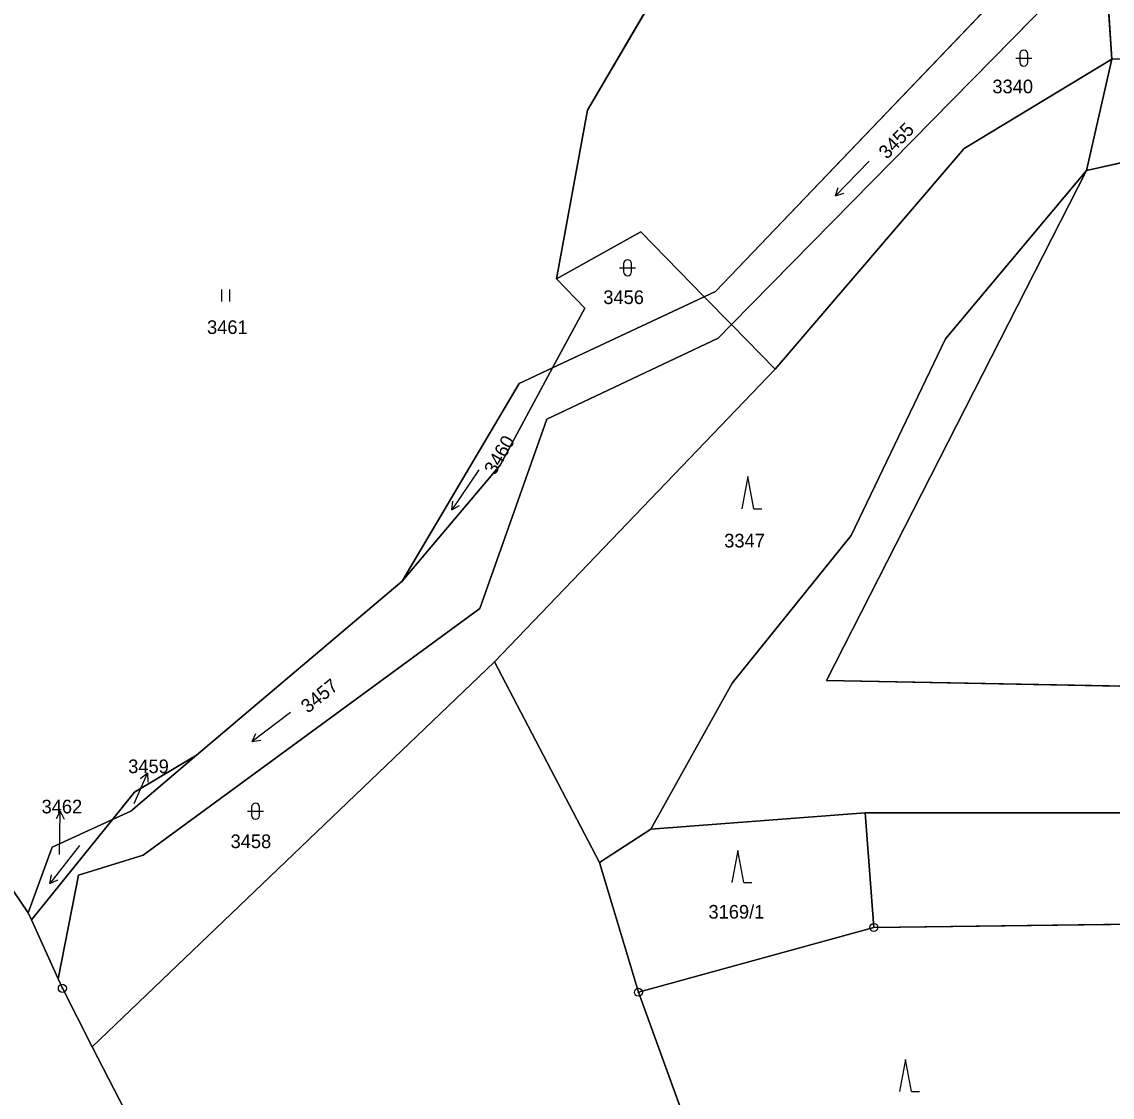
# Model space of a CAD drawing. Extents: x -689422 to -685210, y -987725 to -982160.
# Drawn here: x -688480.4 to -688344.6, y -984667.7 to -984533.7 of the extents above; entities that cross this region are included whole.
import ezdxf

# ---------------------------------------------------------------- set-up
doc = ezdxf.new("R2010")
doc.units = 0
for name, color, linetype in [('KN_Hranice obce', 7, 'Continuous'), ('KN_Hranice_katastrální území', 7, 'Continuous'), ('KN_Hranice_parcel', 7, 'Continuous'), ('KN_Parcelni cisla', 7, 'Continuous'), ('KN_Parcelni cisla_sipky', 7, 'Continuous'), ('KN_Polygon parcely', 7, 'Continuous'), ('KN_POZEMKY_LESNI POZEMEK', 7, 'Continuous'), ('KN_POZEMKY_OSTATNI PLOCHA', 7, 'Continuous'), ('KN_POZEMKY_TTP', 7, 'Continuous'), ('KN_POZEMKY_VODNI_PLOCHA', 7, 'Continuous'), ('KN_VYUZITI_07_vodni plocha_tok prirozeny', 7, 'Continuous'), ('KN_VYUZITI_27_ostatni plocha_neplodna puda', 7, 'Continuous'), ('KN_Značky bodu BP', 7, 'Continuous'), ('KN_Značky kultur', 7, 'Continuous')]:
    doc.layers.add(name, color=color, linetype=linetype)

msp = doc.modelspace()

# ---------------------------------------------------------------- linework, layer by layer
at = {"layer": 'KN_Hranice obce'}
msp.add_lwpolyline([(-688502.72, -984532.63), (-688500.95, -984546), (-688500.08, -984552.55), (-688496.2, -984562.92), (-688492.04, -984574.01), (-688494.32, -984588.16), (-688498.88, -984616.48), (-688486.18, -984635.03), (-688479.56, -984644.71), (-688479.18, -984645.55), (-688475.85, -984652.92), (-688475.32, -984654.1), (-688471.59, -984661.37), (-688463.53, -984677.08), (-688459.34, -984687.45), (-688479.39, -984708.23), (-688494.26, -984728.04)], dxfattribs=at)
at = {"layer": 'KN_Hranice_katastrální území'}
msp.add_lwpolyline([(-688502.72, -984532.63), (-688500.95, -984546), (-688500.08, -984552.55), (-688496.2, -984562.92), (-688492.04, -984574.01), (-688494.32, -984588.16), (-688498.88, -984616.48), (-688486.18, -984635.03), (-688479.56, -984644.71), (-688479.18, -984645.55), (-688475.85, -984652.92), (-688475.32, -984654.1), (-688471.59, -984661.37), (-688463.53, -984677.08), (-688459.34, -984687.45), (-688479.39, -984708.23), (-688494.26, -984728.04)], dxfattribs=at)
at = {"layer": 'KN_Hranice_parcel'}
for p, q in [((-688393.96, -984567.31), (-688351.07, -984522.41)), ((-688344.6, -984538.37), (-688345.32, -984527.81)), ((-688264.04, -984536.89), (-688344.6, -984538.37)), ((-688344.6, -984538.37), (-688347.76, -984552.23)), ((-688347.76, -984552.23), (-688325.28, -984547.24)), ((-688395.37, -984567.97), (-688393.96, -984567.31)), ((-688414.26, -984576.82), (-688395.37, -984567.97)), ((-688395.37, -984567.97), (-688391.99, -984571.43)), ((-688393.64, -984573.11), (-688391.99, -984571.43)), ((-688391.99, -984571.43), (-688386.56, -984576.97)), ((-688386.56, -984576.97), (-688421.5, -984613.44)), ((-688414.26, -984576.82), (-688418.41, -984578.76)), ((-688418.41, -984578.76), (-688433.02, -984603.38)), ((-688433.02, -984603.38), (-688458.61, -984625.07)), ((-688421.5, -984613.44), (-688471.59, -984661.37)), ((-688408.44, -984638.43), (-688421.5, -984613.44)), ((-688402.01, -984634.28), (-688375.35, -984632.24)), ((-688375.35, -984632.24), (-688374.25, -984646.51)), ((-688283.04, -984632.26), (-688375.35, -984632.24)), ((-688469.06, -984633.06), (-688479.18, -984645.55)), ((-688476.58, -984636.51), (-688469.06, -984633.06)), ((-688408.44, -984638.43), (-688402.01, -984634.28)), ((-688486.18, -984635.03), (-688479.56, -984644.71)), ((-688479.56, -984644.71), (-688476.58, -984636.51)), ((-688403.58, -984654.59), (-688408.44, -984638.43)), ((-688479.56, -984644.71), (-688479.18, -984645.55)), ((-688479.18, -984645.55), (-688475.85, -984652.92)), ((-688403.58, -984654.59), (-688374.25, -984646.51)), ((-688475.85, -984652.92), (-688475.32, -984654.1)), ((-688475.32, -984654.1), (-688471.59, -984661.37)), ((-688386.37, -984701.91), (-688403.58, -984654.59)), ((-688471.59, -984661.37), (-688463.53, -984677.08))]:
    msp.add_line(p, q, dxfattribs=at)
for points in [[(-688389.76, -984517.46), (-688397.31, -984523.2), (-688409.93, -984544.71), (-688413.76, -984565.73)], [(-688345.32, -984527.81), (-688349.54, -984528.23), (-688391.99, -984571.43)], [(-688386.56, -984576.97), (-688363, -984549.48), (-688344.6, -984538.37)], [(-688325.28, -984547.24), (-688269.48, -984546.51), (-688283.23, -984617.59), (-688380.15, -984615.76), (-688347.76, -984552.23)], [(-688347.76, -984552.23), (-688365.33, -984573.19), (-688377.06, -984597.71), (-688391.91, -984616.11), (-688402.01, -984634.28)], [(-688413.76, -984565.73), (-688403.27, -984559.89), (-688395.37, -984567.97)], [(-688413.76, -984565.73), (-688410.25, -984569.39), (-688414.26, -984576.82)], [(-688475.85, -984652.92), (-688473.33, -984640), (-688465.25, -984637.52), (-688423.32, -984606.79), (-688414.98, -984583.19), (-688393.64, -984573.11)], [(-688414.26, -984576.82), (-688420.8, -984588.94), (-688433.02, -984603.38)], [(-688458.61, -984625.07), (-688466.81, -984632.02), (-688469.06, -984633.06)], [(-688458.61, -984625.07), (-688466.33, -984629.68), (-688469.06, -984633.06)], [(-688374.25, -984646.51), (-688339.25, -984646.06), (-688339.83, -984661.97)]]:
    msp.add_lwpolyline(points, dxfattribs=at)
at = {"layer": 'KN_Parcelni cisla_sipky'}
for p, q in [((-688465.93, -984630.03), (-688464.71, -984627.29)), ((-688464.71, -984627.29), (-688465.57, -984628)), ((-688464.71, -984627.29), (-688464.66, -984628.41)), ((-688466.39, -984631.07), (-688465.93, -984630.03)), ((-688475.58, -984632.02), (-688476.1, -984633.01)), ((-688475.63, -984635.02), (-688475.58, -984632.02)), ((-688475.58, -984632.02), (-688475.09, -984633.03)), ((-688475.68, -984637.43), (-688475.63, -984635.02))]:
    msp.add_line(p, q, dxfattribs=at)
at = {"layer": 'KN_Polygon parcely'}
for points in [[(-688391.99, -984571.43), (-688349.54, -984528.23), (-688345.32, -984527.81), (-688345.35, -984525.63), (-688339.26, -984521.78), (-688328.95, -984520.44), (-688351.07, -984522.41), (-688393.96, -984567.31), (-688395.37, -984567.97)], [(-688282.78, -984521.59), (-688286.16, -984521.96), (-688345.32, -984527.81), (-688344.6, -984538.37), (-688264.04, -984536.89), (-688262.67, -984524.58)], [(-688386.56, -984576.97), (-688363, -984549.48), (-688344.6, -984538.37), (-688345.32, -984527.81), (-688349.54, -984528.23), (-688391.99, -984571.43)], [(-688344.6, -984538.37), (-688347.76, -984552.23), (-688325.28, -984547.24), (-688310.8, -984539.52), (-688264.46, -984540.61), (-688264.04, -984536.89)], [(-688402.01, -984634.28), (-688391.91, -984616.11), (-688377.06, -984597.71), (-688365.33, -984573.19), (-688347.76, -984552.23), (-688344.6, -984538.37), (-688363, -984549.48), (-688386.56, -984576.97), (-688421.5, -984613.44), (-688408.44, -984638.43)], [(-688264.46, -984540.61), (-688310.8, -984539.52), (-688325.28, -984547.24), (-688269.48, -984546.51), (-688283.23, -984617.59), (-688380.15, -984615.76), (-688347.76, -984552.23), (-688365.33, -984573.19), (-688377.06, -984597.71), (-688391.91, -984616.11), (-688402.01, -984634.28), (-688375.35, -984632.24), (-688283.04, -984632.26)], [(-688347.76, -984552.23), (-688380.15, -984615.76), (-688283.23, -984617.59), (-688269.48, -984546.51), (-688325.28, -984547.24)], [(-688414.26, -984576.82), (-688395.37, -984567.97), (-688403.27, -984559.89), (-688413.76, -984565.73), (-688410.25, -984569.39)], [(-688420.8, -984588.94), (-688433.02, -984603.38), (-688458.61, -984625.07), (-688466.81, -984632.02), (-688469.06, -984633.06), (-688479.18, -984645.55), (-688475.85, -984652.92), (-688473.33, -984640), (-688465.25, -984637.52), (-688423.32, -984606.79), (-688414.98, -984583.19), (-688393.64, -984573.11), (-688391.99, -984571.43), (-688395.37, -984567.97), (-688414.26, -984576.82)], [(-688471.59, -984661.37), (-688421.5, -984613.44), (-688386.56, -984576.97), (-688391.99, -984571.43), (-688393.64, -984573.11), (-688414.98, -984583.19), (-688423.32, -984606.79), (-688465.25, -984637.52), (-688473.33, -984640), (-688475.85, -984652.92), (-688475.32, -984654.1)], [(-688433.02, -984603.38), (-688420.8, -984588.94), (-688414.26, -984576.82), (-688418.41, -984578.76)], [(-688386.37, -984701.91), (-688403.58, -984654.59), (-688408.44, -984638.43), (-688421.5, -984613.44), (-688471.59, -984661.37), (-688463.53, -984677.08), (-688459.34, -984687.45), (-688430.5, -984736.06), (-688410.52, -984717.05), (-688390.36, -984704.33)], [(-688469.06, -984633.06), (-688466.81, -984632.02), (-688458.61, -984625.07), (-688466.33, -984629.68)], [(-688374.25, -984646.51), (-688375.35, -984632.24), (-688402.01, -984634.28), (-688408.44, -984638.43), (-688403.58, -984654.59)], [(-688283.04, -984632.26), (-688375.35, -984632.24), (-688374.25, -984646.51), (-688339.25, -984646.06), (-688339.83, -984661.97), (-688289.9, -984666.83)], [(-688479.18, -984645.55), (-688469.06, -984633.06), (-688476.58, -984636.51), (-688479.56, -984644.71)], [(-688373.26, -984693.97), (-688358.53, -984688.95), (-688347.01, -984687.83), (-688343.07, -984688.32), (-688339.83, -984661.97), (-688339.25, -984646.06), (-688374.25, -984646.51), (-688403.58, -984654.59), (-688386.37, -984701.91)]]:
    msp.add_lwpolyline(points, close=True, dxfattribs=at)
for points in [[(-688397.31, -984523.2), (-688409.93, -984544.71), (-688413.76, -984565.73), (-688403.27, -984559.89), (-688395.37, -984567.97), (-688393.96, -984567.31), (-688351.07, -984522.41)], [(-688502.72, -984532.63), (-688500.95, -984546), (-688500.08, -984552.55), (-688496.2, -984562.92), (-688492.04, -984574.01), (-688494.32, -984588.16), (-688498.88, -984616.48), (-688486.18, -984635.03), (-688479.56, -984644.71), (-688476.58, -984636.51), (-688469.06, -984633.06), (-688466.33, -984629.68), (-688458.61, -984625.07), (-688433.02, -984603.38), (-688418.41, -984578.76), (-688414.26, -984576.82), (-688410.25, -984569.39), (-688413.76, -984565.73), (-688409.93, -984544.71), (-688397.31, -984523.2)]]:
    msp.add_lwpolyline(points, dxfattribs=at)
at = {"layer": 'KN_POZEMKY_LESNI POZEMEK'}
for p, q in [((-688363, -984549.48), (-688344.6, -984538.37)), ((-688344.6, -984538.37), (-688347.76, -984552.23)), ((-688386.56, -984576.97), (-688363, -984549.48)), ((-688347.76, -984552.23), (-688380.15, -984615.76)), ((-688365.33, -984573.19), (-688347.76, -984552.23)), ((-688347.76, -984552.23), (-688365.33, -984573.19)), ((-688377.06, -984597.71), (-688365.33, -984573.19)), ((-688365.33, -984573.19), (-688377.06, -984597.71)), ((-688421.5, -984613.44), (-688386.56, -984576.97)), ((-688391.91, -984616.11), (-688377.06, -984597.71)), ((-688377.06, -984597.71), (-688391.91, -984616.11)), ((-688471.59, -984661.37), (-688421.5, -984613.44)), ((-688421.5, -984613.44), (-688408.44, -984638.43)), ((-688408.44, -984638.43), (-688421.5, -984613.44)), ((-688402.01, -984634.28), (-688391.91, -984616.11)), ((-688391.91, -984616.11), (-688402.01, -984634.28)), ((-688380.15, -984615.76), (-688283.23, -984617.59)), ((-688402.01, -984634.28), (-688375.35, -984632.24)), ((-688375.35, -984632.24), (-688402.01, -984634.28)), ((-688375.35, -984632.24), (-688374.25, -984646.51)), ((-688374.25, -984646.51), (-688375.35, -984632.24)), ((-688375.35, -984632.24), (-688283.04, -984632.26)), ((-688283.04, -984632.26), (-688375.35, -984632.24)), ((-688408.44, -984638.43), (-688402.01, -984634.28)), ((-688402.01, -984634.28), (-688408.44, -984638.43)), ((-688403.58, -984654.59), (-688408.44, -984638.43)), ((-688408.44, -984638.43), (-688403.58, -984654.59)), ((-688374.25, -984646.51), (-688403.58, -984654.59)), ((-688403.58, -984654.59), (-688374.25, -984646.51)), ((-688374.25, -984646.51), (-688339.25, -984646.06)), ((-688339.25, -984646.06), (-688374.25, -984646.51)), ((-688386.37, -984701.91), (-688403.58, -984654.59)), ((-688403.58, -984654.59), (-688386.37, -984701.91)), ((-688463.53, -984677.08), (-688471.59, -984661.37))]:
    msp.add_line(p, q, dxfattribs=at)
at = {"layer": 'KN_POZEMKY_OSTATNI PLOCHA'}
for p, q in [((-688351.07, -984522.41), (-688393.96, -984567.31)), ((-688409.93, -984544.71), (-688397.31, -984523.2)), ((-688391.99, -984571.43), (-688349.54, -984528.23)), ((-688345.32, -984527.81), (-688344.6, -984538.37)), ((-688344.6, -984538.37), (-688345.32, -984527.81)), ((-688264.04, -984536.89), (-688344.6, -984538.37)), ((-688344.6, -984538.37), (-688264.04, -984536.89)), ((-688344.6, -984538.37), (-688363, -984549.48)), ((-688347.76, -984552.23), (-688344.6, -984538.37)), ((-688413.76, -984565.73), (-688409.93, -984544.71)), ((-688325.28, -984547.24), (-688347.76, -984552.23)), ((-688363, -984549.48), (-688386.56, -984576.97)), ((-688413.76, -984565.73), (-688403.27, -984559.89)), ((-688403.27, -984559.89), (-688413.76, -984565.73)), ((-688403.27, -984559.89), (-688395.37, -984567.97)), ((-688395.37, -984567.97), (-688403.27, -984559.89)), ((-688410.25, -984569.39), (-688413.76, -984565.73)), ((-688393.96, -984567.31), (-688395.37, -984567.97)), ((-688395.37, -984567.97), (-688414.26, -984576.82)), ((-688414.26, -984576.82), (-688410.25, -984569.39)), ((-688393.64, -984573.11), (-688391.99, -984571.43)), ((-688386.56, -984576.97), (-688391.99, -984571.43)), ((-688391.99, -984571.43), (-688386.56, -984576.97)), ((-688414.98, -984583.19), (-688393.64, -984573.11)), ((-688386.56, -984576.97), (-688421.5, -984613.44)), ((-688423.32, -984606.79), (-688414.98, -984583.19)), ((-688465.25, -984637.52), (-688423.32, -984606.79)), ((-688421.5, -984613.44), (-688471.59, -984661.37)), ((-688458.61, -984625.07), (-688466.81, -984632.02)), ((-688466.33, -984629.68), (-688458.61, -984625.07)), ((-688469.06, -984633.06), (-688466.33, -984629.68)), ((-688466.81, -984632.02), (-688469.06, -984633.06)), ((-688473.33, -984640), (-688465.25, -984637.52)), ((-688475.85, -984652.92), (-688473.33, -984640)), ((-688475.32, -984654.1), (-688475.85, -984652.92)), ((-688471.59, -984661.37), (-688475.32, -984654.1))]:
    msp.add_line(p, q, dxfattribs=at)
at = {"layer": 'KN_POZEMKY_TTP'}
for p, q in [((-688397.31, -984523.2), (-688409.93, -984544.71)), ((-688409.93, -984544.71), (-688413.76, -984565.73)), ((-688347.76, -984552.23), (-688325.28, -984547.24)), ((-688380.15, -984615.76), (-688347.76, -984552.23)), ((-688413.76, -984565.73), (-688410.25, -984569.39)), ((-688410.25, -984569.39), (-688414.26, -984576.82)), ((-688414.26, -984576.82), (-688418.41, -984578.76)), ((-688418.41, -984578.76), (-688433.02, -984603.38)), ((-688433.02, -984603.38), (-688458.61, -984625.07)), ((-688283.23, -984617.59), (-688380.15, -984615.76)), ((-688458.61, -984625.07), (-688466.33, -984629.68)), ((-688466.33, -984629.68), (-688469.06, -984633.06)), ((-688469.06, -984633.06), (-688476.58, -984636.51)), ((-688479.56, -984644.71), (-688486.18, -984635.03)), ((-688476.58, -984636.51), (-688479.56, -984644.71))]:
    msp.add_line(p, q, dxfattribs=at)
at = {"layer": 'KN_POZEMKY_VODNI_PLOCHA'}
for p, q in [((-688393.96, -984567.31), (-688351.07, -984522.41)), ((-688349.54, -984528.23), (-688391.99, -984571.43)), ((-688395.37, -984567.97), (-688393.96, -984567.31)), ((-688414.26, -984576.82), (-688395.37, -984567.97)), ((-688391.99, -984571.43), (-688395.37, -984567.97)), ((-688395.37, -984567.97), (-688391.99, -984571.43)), ((-688391.99, -984571.43), (-688393.64, -984573.11)), ((-688393.64, -984573.11), (-688414.98, -984583.19)), ((-688420.8, -984588.94), (-688414.26, -984576.82)), ((-688414.26, -984576.82), (-688420.8, -984588.94)), ((-688418.41, -984578.76), (-688414.26, -984576.82)), ((-688433.02, -984603.38), (-688418.41, -984578.76)), ((-688414.98, -984583.19), (-688423.32, -984606.79)), ((-688433.02, -984603.38), (-688420.8, -984588.94)), ((-688420.8, -984588.94), (-688433.02, -984603.38)), ((-688458.61, -984625.07), (-688433.02, -984603.38)), ((-688423.32, -984606.79), (-688465.25, -984637.52)), ((-688466.81, -984632.02), (-688458.61, -984625.07)), ((-688469.06, -984633.06), (-688466.81, -984632.02)), ((-688479.18, -984645.55), (-688469.06, -984633.06)), ((-688469.06, -984633.06), (-688479.18, -984645.55)), ((-688476.58, -984636.51), (-688469.06, -984633.06)), ((-688479.56, -984644.71), (-688476.58, -984636.51)), ((-688465.25, -984637.52), (-688473.33, -984640)), ((-688473.33, -984640), (-688475.85, -984652.92)), ((-688479.18, -984645.55), (-688479.56, -984644.71)), ((-688475.85, -984652.92), (-688479.18, -984645.55))]:
    msp.add_line(p, q, dxfattribs=at)
at = {"layer": 'KN_VYUZITI_07_vodni plocha_tok prirozeny'}
for p, q in [((-688393.96, -984567.31), (-688351.07, -984522.41)), ((-688349.54, -984528.23), (-688391.99, -984571.43)), ((-688395.37, -984567.97), (-688393.96, -984567.31)), ((-688414.26, -984576.82), (-688395.37, -984567.97)), ((-688391.99, -984571.43), (-688395.37, -984567.97)), ((-688395.37, -984567.97), (-688391.99, -984571.43)), ((-688391.99, -984571.43), (-688393.64, -984573.11)), ((-688393.64, -984573.11), (-688414.98, -984583.19)), ((-688420.8, -984588.94), (-688414.26, -984576.82)), ((-688414.26, -984576.82), (-688420.8, -984588.94)), ((-688418.41, -984578.76), (-688414.26, -984576.82)), ((-688433.02, -984603.38), (-688418.41, -984578.76)), ((-688414.98, -984583.19), (-688423.32, -984606.79)), ((-688433.02, -984603.38), (-688420.8, -984588.94)), ((-688420.8, -984588.94), (-688433.02, -984603.38)), ((-688458.61, -984625.07), (-688433.02, -984603.38)), ((-688423.32, -984606.79), (-688465.25, -984637.52)), ((-688466.81, -984632.02), (-688458.61, -984625.07)), ((-688469.06, -984633.06), (-688466.81, -984632.02)), ((-688479.18, -984645.55), (-688469.06, -984633.06)), ((-688469.06, -984633.06), (-688479.18, -984645.55)), ((-688476.58, -984636.51), (-688469.06, -984633.06)), ((-688479.56, -984644.71), (-688476.58, -984636.51)), ((-688465.25, -984637.52), (-688473.33, -984640)), ((-688473.33, -984640), (-688475.85, -984652.92)), ((-688479.18, -984645.55), (-688479.56, -984644.71)), ((-688475.85, -984652.92), (-688479.18, -984645.55))]:
    msp.add_line(p, q, dxfattribs=at)
at = {"layer": 'KN_VYUZITI_27_ostatni plocha_neplodna puda'}
for p, q in [((-688351.07, -984522.41), (-688393.96, -984567.31)), ((-688409.93, -984544.71), (-688397.31, -984523.2)), ((-688391.99, -984571.43), (-688349.54, -984528.23)), ((-688345.32, -984527.81), (-688344.6, -984538.37)), ((-688344.6, -984538.37), (-688345.32, -984527.81)), ((-688264.04, -984536.89), (-688344.6, -984538.37)), ((-688344.6, -984538.37), (-688264.04, -984536.89)), ((-688344.6, -984538.37), (-688363, -984549.48)), ((-688347.76, -984552.23), (-688344.6, -984538.37)), ((-688413.76, -984565.73), (-688409.93, -984544.71)), ((-688325.28, -984547.24), (-688347.76, -984552.23)), ((-688363, -984549.48), (-688386.56, -984576.97)), ((-688413.76, -984565.73), (-688403.27, -984559.89)), ((-688403.27, -984559.89), (-688413.76, -984565.73)), ((-688403.27, -984559.89), (-688395.37, -984567.97)), ((-688395.37, -984567.97), (-688403.27, -984559.89)), ((-688410.25, -984569.39), (-688413.76, -984565.73)), ((-688393.96, -984567.31), (-688395.37, -984567.97)), ((-688395.37, -984567.97), (-688414.26, -984576.82)), ((-688414.26, -984576.82), (-688410.25, -984569.39)), ((-688393.64, -984573.11), (-688391.99, -984571.43)), ((-688386.56, -984576.97), (-688391.99, -984571.43)), ((-688391.99, -984571.43), (-688386.56, -984576.97)), ((-688414.98, -984583.19), (-688393.64, -984573.11)), ((-688386.56, -984576.97), (-688421.5, -984613.44)), ((-688423.32, -984606.79), (-688414.98, -984583.19)), ((-688465.25, -984637.52), (-688423.32, -984606.79)), ((-688421.5, -984613.44), (-688471.59, -984661.37)), ((-688458.61, -984625.07), (-688466.81, -984632.02)), ((-688466.33, -984629.68), (-688458.61, -984625.07)), ((-688469.06, -984633.06), (-688466.33, -984629.68)), ((-688466.81, -984632.02), (-688469.06, -984633.06)), ((-688473.33, -984640), (-688465.25, -984637.52)), ((-688475.85, -984652.92), (-688473.33, -984640)), ((-688475.32, -984654.1), (-688475.85, -984652.92)), ((-688471.59, -984661.37), (-688475.32, -984654.1))]:
    msp.add_line(p, q, dxfattribs=at)
at = {"layer": 'KN_Značky bodu BP'}
for centre, radius in [((-688374.25, -984646.51), 0.5), ((-688374.25, -984646.51), 0.0303), ((-688475.32, -984654.1), 0.5), ((-688475.32, -984654.1), 0.0303), ((-688403.58, -984654.59), 0.5), ((-688403.58, -984654.59), 0.0303)]:
    msp.add_circle(centre, radius, dxfattribs=at)
at = {"layer": 'KN_Značky kultur'}
for p, q in [((-688356.08, -984537.74), (-688356.08, -984538.74)), ((-688355.08, -984538.74), (-688355.08, -984537.74)), ((-688356.58, -984538.24), (-688354.58, -984538.24)), ((-688374.85, -984551.08), (-688379.02, -984555.39)), ((-688379.02, -984555.39), (-688378.7, -984554.34)), ((-688379.02, -984555.39), (-688377.98, -984555.04)), ((-688405.92, -984564.35), (-688403.92, -984564.35)), ((-688405.42, -984563.85), (-688405.42, -984564.85)), ((-688404.42, -984564.85), (-688404.42, -984563.85)), ((-688455.45, -984568.54), (-688455.45, -984567.04)), ((-688454.45, -984568.54), (-688454.45, -984567.04)), ((-688423.45, -984589.53), (-688426.8, -984594.51)), ((-688389.94, -984590.37), (-688390.69, -984594.37)), ((-688389.19, -984594.37), (-688389.94, -984590.37)), ((-688426.8, -984594.51), (-688426.67, -984593.42)), ((-688426.8, -984594.51), (-688425.84, -984593.98)), ((-688389.19, -984594.37), (-688388.19, -984594.37)), ((-688446.91, -984619.76), (-688451.7, -984623.37)), ((-688451.7, -984623.37), (-688451.23, -984622.38)), ((-688451.7, -984623.37), (-688450.62, -984623.18)), ((-688451.76, -984631.54), (-688451.76, -984632.54)), ((-688450.76, -984632.54), (-688450.76, -984631.54)), ((-688452.26, -984632.04), (-688450.26, -984632.04)), ((-688473.17, -984636.31), (-688476.86, -984641.04)), ((-688391.19, -984636.93), (-688391.94, -984640.93)), ((-688390.44, -984640.93), (-688391.19, -984636.93)), ((-688476.86, -984641.04), (-688476.66, -984639.96)), ((-688476.86, -984641.04), (-688475.87, -984640.58)), ((-688390.44, -984640.93), (-688389.44, -984640.93)), ((-688370.31, -984662.96), (-688371.06, -984666.96)), ((-688369.56, -984666.96), (-688370.31, -984662.96)), ((-688369.56, -984666.96), (-688368.56, -984666.96))]:
    msp.add_line(p, q, dxfattribs=at)
for centre, start, end in [((-688355.58, -984537.74), 0, 180), ((-688355.58, -984538.74), 180, 359.9879), ((-688404.92, -984563.85), 0, 180), ((-688404.92, -984564.85), 180, 359.9879), ((-688451.26, -984631.54), 0, 180), ((-688451.26, -984632.54), 180, 359.9879)]:
    msp.add_arc(centre, 0.5, start, end, dxfattribs=at)

# ---------------------------------------------------------------- texts
at = {"layer": 'KN_Parcelni cisla'}
for s, p in [('3340', (-688359.49, -984542.62)), ('3456', (-688407.95, -984568.87)), ('3461', (-688457.3, -984572.6)), ('3347', (-688392.89, -984599.19)), ('3459', (-688467.12, -984627.3)), ('3462', (-688477.91, -984632.31)), ('3458', (-688454.37, -984636.64)), ('3169/1', (-688394.85, -984645.42))]:
    msp.add_text(s, height=1.7, dxfattribs=at).set_placement(p)
for s, rotation, p in [('3455', 46, (-688372.61, -984550.92)), ('3460', 60, (-688421.43, -984590.27)), ('3457', 39, (-688444.74, -984619.91))]:
    msp.add_text(s, height=1.7, rotation=rotation, dxfattribs=at).set_placement(p)

doc.saveas('drawing.dxf')
